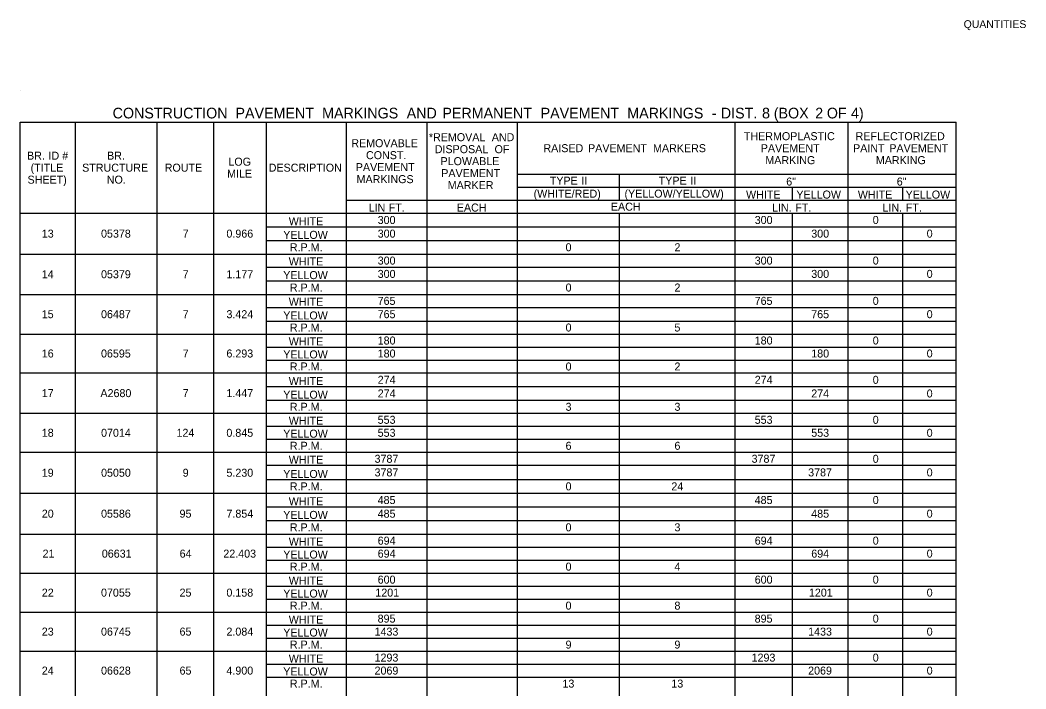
# Model space of a CAD drawing. Extents: x 544420 to 1930787, y -1947044 to 596640.
# Drawn here: x 548756 to 549510, y -1946545 to -1946043 of the extents above; entities that cross this region are included whole.
import ezdxf

# ---------------------------------------------------------------- set-up
doc = ezdxf.new("R2010")
doc.units = 0
doc.layers.add('Default', color=7, linetype='Continuous')
doc.layers.add('R_Border', color=7, linetype='Continuous')

msp = doc.modelspace()

# ---------------------------------------------------------------- linework, layer by layer
at = {"layer": 'Default'}
for p, q in [((548755.58, -1946095.47), (548755.58, -1946095.47)), ((548755.58, -1946119.36), (549457.58, -1946119.36)), ((548755.58, -1946119.36), (549060.75, -1946119.36)), ((548755.58, -1946889.12), (548755.58, -1946119.36)), ((548797.01, -1946878.4), (548797.01, -1946119.36)), ((548858.44, -1946878.4), (548858.44, -1946119.36)), ((548900.85, -1946878.4), (548900.85, -1946119.36)), ((548940.34, -1946878.4), (548940.34, -1946119.36)), ((549000.3, -1946889.12), (549000.3, -1946119.36)), ((549060.75, -1946889.12), (549060.75, -1946119.36)), ((549128.51, -1946889.12), (549128.51, -1946119.36)), ((549291.83, -1946889.12), (549291.83, -1946119.36)), ((549376.65, -1946187.61), (549376.65, -1946119.36)), ((549376.65, -1946889.12), (549376.65, -1946119.36)), ((549457.58, -1946889.12), (549457.58, -1946119.36)), ((549128.51, -1946158.36), (549457.58, -1946158.36)), ((549205.05, -1946177.86), (549205.05, -1946158.36)), ((549128.51, -1946168.11), (549457.58, -1946168.11)), ((549334.73, -1946177.86), (549334.73, -1946168.11)), ((549417.6, -1946177.86), (549417.6, -1946168.11)), ((549000.3, -1946177.86), (549457.58, -1946177.86)), ((549000.3, -1946187.61), (549000.3, -1946177.86)), ((549060.75, -1946187.61), (549060.75, -1946177.86)), ((549128.51, -1946187.61), (549128.51, -1946177.86)), ((548755.58, -1946187.61), (548940.34, -1946187.61)), ((548755.58, -1946187.61), (548900.85, -1946187.61)), ((548900.85, -1946187.61), (549457.58, -1946187.61)), ((549205.05, -1946889.12), (549205.05, -1946187.61)), ((549291.83, -1946187.61), (549376.65, -1946187.61)), ((549334.73, -1946889.12), (549334.73, -1946187.61)), ((549376.65, -1946187.61), (549457.58, -1946187.61)), ((549417.6, -1946889.12), (549417.6, -1946187.61)), ((548940.34, -1946197.85), (549457.58, -1946197.85)), ((548940.34, -1946208.09), (549457.58, -1946208.09)), ((548755.58, -1946218.32), (549457.58, -1946218.32)), ((548940.34, -1946228.07), (549457.58, -1946228.07)), ((548940.34, -1946238.31), (549457.58, -1946238.31)), ((548755.58, -1946248.55), (549457.58, -1946248.55)), ((548940.34, -1946258.3), (549457.58, -1946258.3)), ((548940.34, -1946268.54), (549457.58, -1946268.54)), ((548755.58, -1946278.29), (549457.58, -1946278.29)), ((548940.34, -1946288.04), (549457.58, -1946288.04)), ((548940.34, -1946297.79), (549457.58, -1946297.79)), ((548755.58, -1946307.54), (549457.58, -1946307.54)), ((548940.34, -1946317.77), (549457.58, -1946317.77)), ((548940.34, -1946328.01), (549457.58, -1946328.01)), ((548755.58, -1946337.76), (549457.58, -1946337.76)), ((548940.34, -1946347.51), (549457.58, -1946347.51)), ((548940.34, -1946357.26), (549457.58, -1946357.26)), ((548755.58, -1946367.01), (549457.58, -1946367.01)), ((548940.34, -1946376.76), (549457.58, -1946376.76)), ((548940.34, -1946387.49), (549457.58, -1946387.49)), ((548755.58, -1946397.72), (549457.58, -1946397.72)), ((548940.34, -1946407.96), (549457.58, -1946407.96)), ((548940.34, -1946418.2), (549457.58, -1946418.2)), ((548755.58, -1946428.44), (549457.58, -1946428.44)), ((548940.34, -1946438.19), (549457.58, -1946438.19)), ((548940.34, -1946447.94), (549457.58, -1946447.94)), ((548755.58, -1946457.69), (549457.58, -1946457.69)), ((548940.34, -1946467.44), (549457.58, -1946467.44)), ((548940.34, -1946477.19), (549457.58, -1946477.19)), ((548755.58, -1946486.94), (549457.58, -1946486.94)), ((548940.34, -1946496.69), (549457.58, -1946496.69)), ((548940.34, -1946506.44), (549457.58, -1946506.44)), ((548755.58, -1946516.19), (549457.58, -1946516.19)), ((548940.34, -1946525.94), (549457.58, -1946525.94)), ((548940.34, -1946535.69), (549457.58, -1946535.69))]:
    msp.add_line(p, q, dxfattribs=at)

# ---------------------------------------------------------------- texts
for s, height, p in [('CONSTRUCTION', 8, (548824.96, -1946116.54)), (' PAVEMENT', 8, (548914.12, -1946116.54)), (' MARKINGS', 8, (548979.1, -1946116.54)), (' AND', 8, (549042.52, -1946116.54)), (' PERMANENT', 8, (549069.29, -1946116.54)), (' PAVEMENT', 8, (549142.96, -1946116.54)), (' MARKINGS', 8, (549207.95, -1946116.54)), (' DIST.', 8, (549278.11, -1946116.54)), (' 8', 8, (549309.01, -1946116.54)), (' (BOX', 8, (549317.83, -1946116.54)), (' 2', 8, (549348.87, -1946116.54)), (' OF', 8, (549357.62, -1946116.54)), (' 4)', 8, (549375.73, -1946116.54)), (' -', 8, (549271.37, -1946116.54)), ('*REMOVAL', 6, (549062.13, -1946133.61)), (' AND', 6, (549107.06, -1946133.61)), ('THERMOPLASTIC', 6, (549298.36, -1946132.86)), ('REFLECTORIZED', 6, (549382.15, -1946132.86)), ('REMOVABLE', 6, (549003.95, -1946138.11)), ('BR.', 6, (548760.77, -1946147.49)), (' ID', 6, (548774.63, -1946147.49)), (' #', 6, (548784.93, -1946147.49)), ('BR.', 6, (548820.8, -1946147.49)), ('CONST.', 6, (549014.98, -1946147.11)), ('DISPOSAL', 6, (549066.54, -1946142.61)), (' OF', 6, (549109.15, -1946142.61)), ('RAISED', 6, (549148.02, -1946141.86)), (' PAVEMENT', 6, (549179.28, -1946141.86)), (' MARKERS', 6, (549228.02, -1946141.86)), ('PAVEMENT', 6, (549311.03, -1946141.86)), ('PAINT', 6, (549380.25, -1946141.86)), (' PAVEMENT', 6, (549405.23, -1946141.86)), ('(TITLE', 6, (548763.47, -1946156.49)), ('STRUCTURE', 6, (548802.08, -1946156.49)), ('ROUTE', 6, (548864.02, -1946156.49)), ('LOG', 6, (548911.77, -1946151.99)), ('DESCRIPTION', 6, (548942.01, -1946156.49)), ('PAVEMENT', 6, (549007.32, -1946156.11)), ('PLOWABLE', 6, (549070.86, -1946151.61)), ('MARKING', 6, (549314.47, -1946150.86)), ('MARKING', 6, (549397.34, -1946150.86)), ('MILE', 6, (548910.79, -1946160.99)), ('PAVEMENT', 6, (549071.43, -1946160.61)), ('SHEET)', 6, (548761.14, -1946165.49)), ('NO.', 6, (548820.56, -1946165.49)), ('MARKINGS', 6, (549007.91, -1946165.11)), ('MARKER', 6, (549076.26, -1946169.61)), ('TYPE', 6, (549152.82, -1946166.24)), (' II', 6, (549174.31, -1946166.24)), ('TYPE', 6, (549234.48, -1946166.24)), (' II', 6, (549255.96, -1946166.24)), ('6"', 6, (549330.13, -1946166.91)), ('6"', 6, (549413.01, -1946166.91)), ('(WHITE/RED)', 6, (549140.69, -1946175.99)), ('(YELLOW/YELLOW)', 6, (549208.84, -1946175.99)), ('WHITE', 6, (549299.98, -1946176.66)), ('YELLOW', 6, (549337.76, -1946176.66)), ('WHITE', 6, (549383.83, -1946176.66)), ('YELLOW', 6, (549419.66, -1946176.66)), ('LIN', 6, (549016.95, -1946186.41)), (' FT.', 6, (549029.78, -1946186.41)), ('EACH', 6, (549083.08, -1946186.41)), ('EACH', 6, (549198.61, -1946185.74)), ('LIN.', 6, (549319.45, -1946186.41)), (' FT.', 6, (549334.71, -1946186.41)), ('LIN.', 6, (549402.32, -1946186.41)), (' FT.', 6, (549417.58, -1946186.41)), ('WHITE', 6, (548957.04, -1946196.65)), ('300', 6, (549023.74, -1946195.73)), ('300', 6, (549306.49, -1946195.73)), ('0', 6, (549395, -1946195.73)), ('13', 6, (548771.83, -1946205.97)), ('05378', 6, (548816.26, -1946205.97)), ('7', 6, (548877.51, -1946205.97)), ('0.966', 6, (548910.3, -1946205.97)), ('YELLOW', 6, (548952.9, -1946206.89)), ('300', 6, (549023.74, -1946205.97)), ('300', 6, (549348.9, -1946205.97)), ('0', 6, (549435.46, -1946205.97)), ('R.P.M.', 6, (548957.88, -1946216.2)), ('0', 6, (549164.65, -1946216.2)), ('2', 6, (549246.33, -1946216.2)), ('WHITE', 6, (548957.04, -1946226.87)), ('300', 6, (549023.74, -1946226.2)), ('300', 6, (549306.49, -1946226.2)), ('0', 6, (549395, -1946226.2)), ('14', 6, (548771.84, -1946236.44)), ('05379', 6, (548816.26, -1946236.44)), ('7', 6, (548877.51, -1946236.44)), ('1.177', 6, (548910.3, -1946236.44)), ('YELLOW', 6, (548952.9, -1946237.11)), ('300', 6, (549023.74, -1946236.19)), ('300', 6, (549348.9, -1946236.19)), ('0', 6, (549435.46, -1946236.19)), ('R.P.M.', 6, (548957.88, -1946246.43)), ('0', 6, (549164.65, -1946246.43)), ('2', 6, (549246.33, -1946246.43)), ('WHITE', 6, (548957.04, -1946257.1)), ('765', 6, (549023.7, -1946256.42)), ('765', 6, (549306.45, -1946256.42)), ('0', 6, (549395, -1946256.42)), ('15', 6, (548771.8, -1946266.42)), ('06487', 6, (548816.27, -1946266.42)), ('7', 6, (548877.51, -1946266.42)), ('3.424', 6, (548910.32, -1946266.42)), ('YELLOW', 6, (548952.9, -1946267.34)), ('765', 6, (549023.7, -1946266.42)), ('765', 6, (549348.87, -1946266.42)), ('0', 6, (549435.46, -1946266.42)), ('R.P.M.', 6, (548957.88, -1946276.41)), ('0', 6, (549164.65, -1946276.41)), ('5', 6, (549246.28, -1946276.41)), ('WHITE', 6, (548957.04, -1946286.84)), ('180', 6, (549023.74, -1946286.16)), ('180', 6, (549306.49, -1946286.16)), ('0', 6, (549395, -1946286.16)), ('16', 6, (548771.83, -1946295.91)), ('06595', 6, (548816.24, -1946295.91)), ('7', 6, (548877.51, -1946295.91)), ('6.293', 6, (548910.3, -1946295.91)), ('YELLOW', 6, (548952.9, -1946296.59)), ('180', 6, (549023.74, -1946295.91)), ('180', 6, (549348.9, -1946295.91)), ('0', 6, (549435.46, -1946295.91)), ('R.P.M.', 6, (548957.88, -1946305.66)), ('0', 6, (549164.65, -1946305.66)), ('2', 6, (549246.33, -1946305.66)), ('WHITE', 6, (548957.04, -1946316.57)), ('274', 6, (549023.74, -1946315.65)), ('274', 6, (549306.49, -1946315.65)), ('0', 6, (549395, -1946315.65)), ('17', 6, (548771.83, -1946325.65)), ('A2680', 6, (548815.81, -1946325.65)), ('7', 6, (548877.51, -1946325.65)), ('1.447', 6, (548910.3, -1946325.65)), ('YELLOW', 6, (548952.9, -1946326.81)), ('274', 6, (549023.74, -1946325.89)), ('274', 6, (549348.9, -1946325.89)), ('0', 6, (549435.46, -1946325.89)), ('R.P.M.', 6, (548957.88, -1946335.89)), ('3', 6, (549164.64, -1946335.89)), ('3', 6, (549246.3, -1946335.89)), ('WHITE', 6, (548957.04, -1946346.31)), ('553', 6, (549023.73, -1946345.64)), ('553', 6, (549306.48, -1946345.64)), ('0', 6, (549395, -1946345.64)), ('18', 6, (548771.82, -1946355.39)), ('07014', 6, (548816.28, -1946355.39)), ('124', 6, (548872.86, -1946355.39)), ('0.845', 6, (548910.28, -1946355.39)), ('YELLOW', 6, (548952.9, -1946356.06)), ('553', 6, (549023.73, -1946355.39)), ('553', 6, (549348.89, -1946355.39)), ('0', 6, (549435.46, -1946355.39)), ('R.P.M.', 6, (548957.88, -1946365.14)), ('6', 6, (549164.64, -1946365.14)), ('6', 6, (549246.3, -1946365.14)), ('3787', 6, (549021.4, -1946374.89)), ('3787', 6, (549304.15, -1946374.89)), ('0', 6, (549395, -1946374.89)), ('WHITE', 6, (548957.04, -1946375.56)), ('19', 6, (548771.82, -1946385.37)), ('05050', 6, (548816.28, -1946385.37)), ('9', 6, (548877.5, -1946385.37)), ('5.230', 6, (548910.31, -1946385.37)), ('YELLOW', 6, (548952.9, -1946386.29)), ('3787', 6, (549021.4, -1946385.12)), ('3787', 6, (549346.56, -1946385.12)), ('0', 6, (549435.46, -1946385.12)), ('R.P.M.', 6, (548957.88, -1946395.6)), ('0', 6, (549164.65, -1946395.6)), ('24', 6, (549243.98, -1946395.6)), ('WHITE', 6, (548957.04, -1946406.76)), ('485', 6, (549023.7, -1946405.84)), ('485', 6, (549306.45, -1946405.84)), ('0', 6, (549395, -1946405.84)), ('20', 6, (548771.84, -1946416.08)), ('05586', 6, (548816.27, -1946416.08)), ('95', 6, (548875.15, -1946416.08)), ('7.854', 6, (548910.32, -1946416.08)), ('YELLOW', 6, (548952.9, -1946417)), ('485', 6, (549023.7, -1946416.08)), ('485', 6, (549348.87, -1946416.08)), ('0', 6, (549435.46, -1946416.08)), ('R.P.M.', 6, (548957.88, -1946426.32)), ('0', 6, (549164.65, -1946426.32)), ('3', 6, (549246.3, -1946426.32)), ('WHITE', 6, (548957.04, -1946436.99)), ('694', 6, (549023.74, -1946436.31)), ('694', 6, (549306.49, -1946436.31)), ('0', 6, (549395, -1946436.31)), ('21', 6, (548772.41, -1946446.06)), ('06631', 6, (548816.85, -1946446.06)), ('64', 6, (548875.19, -1946446.06)), ('22.403', 6, (548907.97, -1946446.06)), ('YELLOW', 6, (548952.9, -1946446.74)), ('694', 6, (549023.74, -1946446.06)), ('694', 6, (549348.9, -1946446.06)), ('0', 6, (549435.46, -1946446.06)), ('R.P.M.', 6, (548957.88, -1946455.81)), ('0', 6, (549164.65, -1946455.81)), ('4', 6, (549246.31, -1946455.81)), ('600', 6, (549023.74, -1946465.56)), ('600', 6, (549306.49, -1946465.56)), ('0', 6, (549395, -1946465.56)), ('WHITE', 6, (548957.04, -1946466.24)), ('22', 6, (548771.86, -1946475.31)), ('07055', 6, (548816.24, -1946475.31)), ('25', 6, (548875.15, -1946475.31)), ('0.158', 6, (548910.3, -1946475.31)), ('YELLOW', 6, (548952.9, -1946475.99)), ('1201', 6, (549021.98, -1946475.31)), ('1201', 6, (549347.14, -1946475.31)), ('0', 6, (549435.46, -1946475.31)), ('R.P.M.', 6, (548957.88, -1946485.06)), ('0', 6, (549164.65, -1946485.06)), ('8', 6, (549246.29, -1946485.06)), ('WHITE', 6, (548957.04, -1946495.49)), ('895', 6, (549023.7, -1946494.81)), ('895', 6, (549306.45, -1946494.81)), ('0', 6, (549395, -1946494.81)), ('23', 6, (548771.83, -1946504.56)), ('06745', 6, (548816.24, -1946504.56)), ('65', 6, (548875.15, -1946504.56)), ('2.084', 6, (548910.32, -1946504.56)), ('YELLOW', 6, (548952.9, -1946505.24)), ('1433', 6, (549021.4, -1946504.56)), ('1433', 6, (549346.56, -1946504.56)), ('0', 6, (549435.46, -1946504.56)), ('R.P.M.', 6, (548957.88, -1946514.31)), ('9', 6, (549164.64, -1946514.31)), ('9', 6, (549246.29, -1946514.31)), ('WHITE', 6, (548957.04, -1946524.74)), ('1293', 6, (549021.4, -1946524.06)), ('1293', 6, (549304.15, -1946524.06)), ('0', 6, (549395, -1946524.06)), ('24', 6, (548771.84, -1946533.81)), ('06628', 6, (548816.26, -1946533.81)), ('65', 6, (548875.15, -1946533.81)), ('4.900', 6, (548910.31, -1946533.81)), ('YELLOW', 6, (548952.9, -1946534.49)), ('2069', 6, (549021.39, -1946533.81)), ('2069', 6, (549346.55, -1946533.81)), ('0', 6, (549435.46, -1946533.81)), ('R.P.M.', 6, (548957.88, -1946543.56)), ('13', 6, (549162.31, -1946543.56)), ('13', 6, (549243.97, -1946543.56))]:
    msp.add_text(s, height=height, dxfattribs=at).set_placement(p)
at = {"layer": 'R_Border'}
msp.add_text('QUANTITIES', height=5.862, rotation=360, dxfattribs=at).set_placement((549463.18, -1946048.73))

doc.saveas('drawing.dxf')
